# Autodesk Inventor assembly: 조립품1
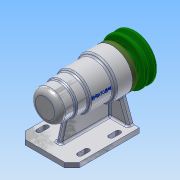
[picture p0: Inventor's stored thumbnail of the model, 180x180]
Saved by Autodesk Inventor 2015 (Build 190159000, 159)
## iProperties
Created: 2017-09
Part Number: 조립품1
Document SubType Name: Assembly
Designer: 김선찬
Author: 김선찬
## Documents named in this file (12)
- C:\Users\김선찬\Desktop\470908V1014\조립품1.iam
- C:\Users\김선찬\Desktop\470908V1014\본체1.ipt
- C:\Users\김선찬\Desktop\470908V1014\V벨트풀리.ipt
- C:\Users\김선찬\Desktop\470908V1014\멈춤나사 M3x8.ipt
- C:\Users\김선찬\Desktop\470908V1014\베어링 6004.ipt
- C:\Users\김선찬\Desktop\470908V1014\베어링 51202.ipt
- C:\Users\김선찬\Desktop\470908V1014\볼트 M4 x 12.ipt
- C:\Users\김선찬\Desktop\470908V1014\어댑터슬리브.ipt
- C:\Users\김선찬\Desktop\470908V1014\오일 실 20x35x7.ipt
- C:\Users\김선찬\Desktop\470908V1014\축.ipt
- C:\Users\김선찬\Desktop\470908V1014\커버.ipt
- C:\Users\김선찬\Desktop\470908V1014\키 5 x 5 x 16.ipt
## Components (1 placed, 1 different names)
1. V벨트풀리:1 — 각도:1
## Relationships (1: Angle 1)
- 각도:1 [Angle]: V벨트풀리:1
